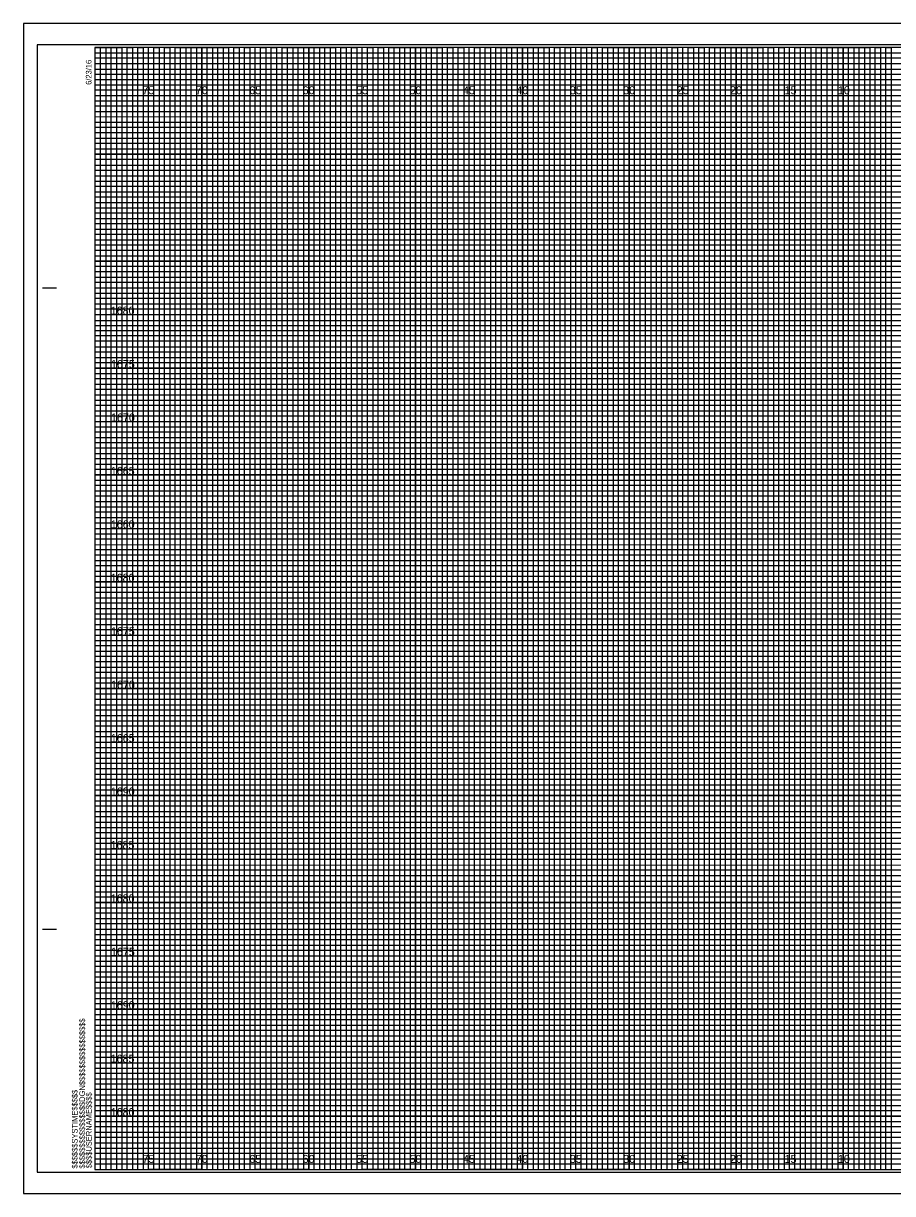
# Model space of a CAD drawing. Extents: x -7 to 162, y -2 to 107.
# Drawn here: x -6.7 to 74.6, y -2.3 to 107.3 of the extents above; entities that cross this region are included whole.
import ezdxf

# ---------------------------------------------------------------- set-up
doc = ezdxf.new("R2010")
doc.units = 0
for name, color, linetype in [('Prop XS Elevation Labels', 7, 'Continuous'), ('Prop XS Offset Labels', 7, 'Continuous'), ('Sheet Cross Section CELL', 7, 'Continuous'), ('Sheet Cross Section Grid Major CELL', 7, 'Continuous'), ('Sheet Cross Section Grid Middle CELL', 7, 'Continuous'), ('Sheet Cross Section Grid Minor 1 CELL', 7, 'Continuous'), ('Sheet Cross Section Grid Minor 2 CELL', 7, 'Continuous'), ('Sheet Cutting Line CELL', 7, 'Continuous'), ('Sheet DOT Grid CELL', 7, 'Continuous'), ('Sheet Plot Border Inside CELL', 7, 'Continuous'), ('Sheet Plot Border Outside CELL', 7, 'Continuous')]:
    doc.layers.add(name, color=color, linetype=linetype)

msp = doc.modelspace()

# ---------------------------------------------------------------- linework, layer by layer
at = {"layer": 'Sheet Cross Section CELL'}
for p, q in [((-4.9, 82.5), (-3.65, 82.5)), ((-4.85, 82.5), (-3.6, 82.5)), ((-4.9, 22.5), (-3.65, 22.5)), ((-4.85, 22.5), (-3.6, 22.5)), ((0, 0), (0, 0)), ((0, 0), (0, 0)), ((0, 0), (0, 0)), ((0, 0), (0, 0)), ((0, 0), (0, 0)), ((0, 0), (0, 0)), ((0, 0), (0, 0))]:
    msp.add_line(p, q, dxfattribs=at)
msp.add_lwpolyline([(160, 105), (0, 105), (0, 0), (160, 0)], close=True, dxfattribs=at)
at = {"layer": 'Sheet Cross Section Grid Major CELL'}
for p, q in [((5, 105), (0, 105)), ((5, 0), (5, 105)), ((15, 105), (10, 105)), ((10, 105), (10, 0)), ((15, 0), (15, 105)), ((25, 105), (20, 105)), ((20, 105), (20, 0)), ((25, 0), (25, 105)), ((35, 105), (30, 105)), ((30, 105), (30, 0)), ((35, 0), (35, 105)), ((45, 105), (40, 105)), ((40, 105), (40, 0)), ((45, 0), (45, 105)), ((55, 105), (50, 105)), ((50, 105), (50, 0)), ((55, 0), (55, 105)), ((65, 105), (60, 105)), ((60, 105), (60, 0)), ((65, 0), (65, 105)), ((75, 105), (70, 105)), ((70, 105), (70, 0)), ((10, 0), (5, 0)), ((20, 0), (15, 0)), ((30, 0), (25, 0)), ((40, 0), (35, 0)), ((50, 0), (45, 0)), ((60, 0), (55, 0)), ((70, 0), (65, 0))]:
    msp.add_line(p, q, dxfattribs=at)
for points in [[(0, 100), (160, 100), (160, 95), (0, 95)], [(0, 90), (160, 90), (160, 85), (0, 85)], [(0, 80), (160, 80), (160, 75), (0, 75)], [(0, 70), (160, 70), (160, 65), (0, 65)], [(0, 60), (160, 60), (160, 55), (0, 55)], [(0, 50), (160, 50), (160, 45), (0, 45)], [(0, 40), (160, 40), (160, 35), (0, 35)], [(0, 30), (160, 30), (160, 25), (0, 25)], [(0, 20), (160, 20), (160, 15), (0, 15)], [(0, 10), (160, 10), (160, 5), (0, 5)]]:
    msp.add_lwpolyline(points, dxfattribs=at)
at = {"layer": 'Sheet Cross Section Grid Middle CELL'}
for points in [[(0, 105), (2.5, 105), (2.5, 0), (7.5, 0), (7.5, 105), (12.5, 105), (12.5, 0), (17.5, 0), (17.5, 105), (22.5, 105), (22.5, 0), (27.5, 0), (27.5, 105), (32.5, 105), (32.5, 0), (37.5, 0), (37.5, 105), (42.5, 105), (42.5, 0), (47.5, 0), (47.5, 105), (52.5, 105), (52.5, 0), (57.5, 0), (57.5, 105), (62.5, 105), (62.5, 0), (67.5, 0), (67.5, 105), (72.5, 105), (72.5, 0), (77.5, 0)], [(0, 102.5), (137.5, 102.5)], [(0, 92.5), (160, 92.5), (160, 97.5), (0, 97.5)], [(0, 82.5), (160, 82.5), (160, 87.5), (0, 87.5)], [(0, 72.5), (160, 72.5), (160, 77.5), (0, 77.5)], [(0, 62.5), (160, 62.5), (160, 67.5), (0, 67.5)], [(0, 52.5), (160, 52.5), (160, 57.5), (0, 57.5)], [(0, 42.5), (160, 42.5), (160, 47.5), (0, 47.5)], [(0, 32.5), (160, 32.5), (160, 37.5), (0, 37.5)], [(0, 22.5), (160, 22.5), (160, 27.5), (0, 27.5)], [(0, 12.5), (160, 12.5), (160, 17.5), (0, 17.5)], [(0, 2.5), (160, 2.5), (160, 7.5), (0, 7.5)]]:
    msp.add_lwpolyline(points, dxfattribs=at)
at = {"layer": 'Sheet Cross Section Grid Minor 1 CELL'}
for p, q in [((0, 104.5), (130, 104.5)), ((130, 103.99), (0, 103.99)), ((0, 103.99), (0, 103.5)), ((0, 103.5), (130, 103.5)), ((130, 102.95), (0, 102.95)), ((0, 102.95), (0, 102)), ((0, 102), (160, 102))]:
    msp.add_line(p, q, dxfattribs=at)
for points in [[(0, 101.5), (135, 101.5), (160, 101.5), (160, 101), (0, 101)], [(0, 100.5), (160, 100.5), (160, 99.5), (0, 99.5)], [(0, 99), (160, 99), (160, 98.5), (0, 98.49)], [(0, 98), (160, 98), (160, 97), (0, 97)], [(0, 96.5), (160, 96.5), (160, 96), (0, 96)], [(0, 95.5), (160, 95.5), (160, 94.5), (0, 94.5)], [(0, 94), (160, 94), (160, 93.5), (0, 93.5)], [(0, 93), (160, 93), (160, 92), (0, 92)], [(0, 91.5), (160, 91.5), (160, 91), (0, 91)], [(0, 90.5), (160, 90.5), (160, 89.5), (0, 89.5)], [(0, 89), (160, 89), (160, 88.5), (0, 88.5)], [(0, 88), (160, 88), (160, 86.98), (160, 86.5), (160, 86), (0, 86)], [(0, 87), (160, 87), (160, 86.5), (0, 86.5)], [(0, 85.5), (160, 85.5), (160, 84.5), (0, 84.52)], [(0, 84.52), (160, 84.5), (160, 84), (0, 84)], [(0, 83.5), (160, 83.5), (160, 83), (0, 83)], [(0, 82), (160, 82), (160, 81.5), (0, 81.5)], [(0, 81), (160, 81), (160, 80.5), (0, 80.5)], [(-0.04, 79.45), (160, 79.45), (160, 78.94), (-0.04, 78.94)], [(0, 78.5), (160, 78.5), (160, 78), (0, 78)], [(0, 77), (160, 77), (160, 76.5), (0, 76.5)], [(0, 76), (160, 76), (160, 75.5), (0, 75.5)], [(0, 74.5), (160, 74.5), (160, 74), (0, 74)], [(0, 73.5), (160, 73.5), (160, 73), (0, 73)], [(0, 72), (160, 72), (160, 71.5), (0, 71.5)], [(0, 71), (160, 71), (160, 70.5), (0, 70.5)], [(0, 69.5), (160, 69.5), (160, 68.99), (0, 69)], [(0, 68.5), (160, 68.5), (160, 68), (0, 68)], [(0, 67), (160, 67), (160, 66.5), (0, 66.5)], [(0, 66), (160, 66), (160, 65.5), (0, 65.5)], [(0, 64.5), (160, 64.5), (160, 64), (0, 64)], [(0, 63.5), (160, 63.5), (160, 63), (0, 63)], [(0, 62), (160, 62), (160, 61.5), (0, 61.5)], [(0, 61), (160, 61), (160, 60.5), (0, 60.5)], [(0, 59.5), (160, 59.5), (160, 59), (0, 59)], [(0, 58.5), (160.03, 58.45), (160, 58), (0, 58)], [(0, 57), (160, 57), (160, 56.5), (0, 56.5)], [(0, 56), (160, 56), (160, 55.5), (0, 55.5)], [(0, 54.5), (160, 54.5), (160, 54), (0, 54)], [(0, 53.5), (160, 53.5), (160, 53), (0, 53)], [(0, 52), (160, 52), (160, 51.5), (0, 51.5)], [(0, 51), (160, 51), (160, 50.5), (0, 50.5)], [(0, 49.5), (160, 49.5), (160, 49), (0, 49)], [(0, 48.5), (160, 48.5), (160, 48), (0, 48)], [(0, 47), (160, 47), (160, 46.5), (0, 46.5)], [(0, 46), (160, 46), (160, 45.5), (0, 45.5)], [(0, 44.5), (160, 44.5), (160, 44), (0, 44)], [(0, 43.5), (160, 43.5), (160, 43), (0, 43)], [(0, 42), (160, 42), (160, 41.5), (0, 41.5)], [(0, 41), (160, 41), (160, 40.5), (0, 40.5)], [(0, 39.5), (160, 39.5), (160, 38.99), (0, 39)], [(0, 38.5), (160, 38.5), (160, 38), (0, 38)], [(0, 37), (160, 37), (160, 36.5), (0, 36.5)], [(0, 36), (160, 36), (160, 35.5), (0, 35.5)], [(0, 34.5), (160, 34.5), (160, 34), (0, 34)], [(0, 33.5), (160, 33.5), (160, 33), (0, 33)], [(0, 32), (160, 32), (160, 31.5), (0, 31.5)], [(0, 31), (160, 31), (160, 30.5), (0, 30.5)], [(0, 29.5), (160, 29.5), (160, 29), (0, 29)], [(0, 28.5), (160.03, 28.46), (160, 28), (0, 28)], [(0, 27), (160, 27), (160, 26.5), (0, 26.5)], [(0, 26), (160, 26), (160, 25.5), (0, 25.5)], [(0, 24.5), (160, 24.5), (160, 24), (0, 24)], [(0, 23.5), (160, 23.5), (160, 23), (0, 23)], [(0, 22), (160, 22), (160, 21.5), (0, 21.5)], [(0, 21), (160, 21), (160, 20.5), (0, 20.5)], [(0, 19.5), (160, 19.5), (160, 19), (0, 19)], [(0, 18.5), (160, 18.5), (160, 18), (0, 18)], [(0, 17), (160, 17), (160, 16.5), (0, 16.5)], [(0, 16), (160, 16), (160, 15.5), (0, 15.5)], [(0, 14.5), (160, 14.5), (160, 14), (0, 14)], [(0, 13.5), (160, 13.5), (160, 13), (0, 13)], [(0, 12), (160, 12), (160, 11.5), (0, 11.5)], [(0, 11), (160, 11), (160, 10.5), (0, 10.5)], [(0, 9.5), (160, 9.5), (160, 9), (0, 9)], [(0, 8.5), (160, 8.5), (160, 8), (0, 8)], [(0, 7), (160, 7), (160, 6.5), (0, 6.5)], [(0, 6), (160, 6), (160, 5.5), (0, 5.5)], [(0, 4.5), (160, 4.5), (160, 4), (0, 4)], [(0, 3.5), (160, 3.5), (160, 3), (0, 3)], [(0, 2), (160, 2), (160, 1.5), (0, 1.5)], [(0, 1), (160, 1), (160, 0.5), (0, 0.5)]]:
    msp.add_lwpolyline(points, dxfattribs=at)
at = {"layer": 'Sheet Cross Section Grid Minor 2 CELL'}
for points in [[(0, 0), (0.5, 0), (0.5, 105), (1, 105), (1, 0)], [(1, 0), (1.5, 0), (1.5, 105), (2, 105), (2, 0)], [(2.5, 0), (3, 0), (3, 105), (3.5, 105), (3.5, 0)], [(3.5, 0), (4, 0), (4, 105), (4.5, 105), (4.5, 0)], [(5, 0), (5.5, 0), (5.5, 105), (6, 105), (6, 0)], [(6, 0), (6.5, 0), (6.5, 105), (7, 105), (7, 0)], [(7.5, 0), (8, 0), (8, 105), (8.5, 105), (8.5, 0)], [(8.5, 0), (9, 0), (9, 105), (9.5, 105), (9.5, 0)], [(10, 0), (10.5, 0), (10.5, 105), (11, 105), (11, 0)], [(11, 0), (11.5, 0), (11.5, 105), (12, 105), (12, 0)], [(12.5, 0), (13, 0), (13, 105), (13.5, 105), (13.5, 0)], [(13.5, 0), (14, 0), (14, 105), (14.5, 105), (14.5, 0)], [(15, 0), (15.5, 0), (15.5, 105), (16, 105), (16, 0)], [(16, 0), (16.5, 0), (16.5, 105), (17, 105), (17, 0)], [(17.5, 0), (18, 0), (18, 105), (18.5, 105), (18.5, 0)], [(18.5, 0), (19, 0), (19, 105), (19.5, 105), (19.5, 0)], [(20, 0), (20.5, 0), (20.5, 105), (21, 105), (21, 0)], [(21, 0), (21.5, 0), (21.5, 105), (22, 105), (22, 0)], [(22.5, 0), (23, 0), (23, 105), (23.5, 105), (23.5, 0)], [(23.5, 0), (24, 0), (24, 105), (24.5, 105), (24.5, 0)], [(25, 0), (25.5, 0), (25.5, 105), (26, 105), (26, 0)], [(26, 0), (26.5, 0), (26.5, 105), (27, 105), (27, 0)], [(27.5, 0), (28, 0), (28, 105), (28.5, 105), (28.5, 0)], [(28.5, 0), (29, 0), (29, 105), (29.5, 105), (29.5, 0)], [(30, 0), (30.5, 0), (30.5, 105), (31, 105), (31, 0)], [(31, 0), (31.5, 0), (31.5, 105), (32, 105), (32, 0)], [(32.5, 0), (33, 0), (33, 105), (33.5, 105), (33.5, 0)], [(33.5, 0), (34, 0), (34, 105), (34.5, 105), (34.5, 0)], [(35, 0), (35.5, 0), (35.5, 105), (36, 105), (36, 0)], [(36, 0), (36.5, 0), (36.5, 105), (37, 105), (37, 0)], [(37.5, 0), (38, 0), (38, 105), (38.5, 105), (38.5, 0)], [(38.5, 0), (39, 0), (39, 105), (39.5, 105), (39.5, 0)], [(40, 0), (40.5, 0), (40.5, 105), (41, 105), (41, 0)], [(41, 0), (41.5, 0), (41.5, 105), (42, 105), (42, 0)], [(42.5, 0), (43, 0), (43, 105), (43.5, 105), (43.5, 0)], [(43.5, 0), (44, 0), (44, 105), (44.5, 105), (44.5, 0)], [(45, 0), (45.5, 0), (45.5, 105), (46, 105), (46, 0)], [(46, 0), (46.5, 0), (46.5, 105), (47, 105), (47, 0)], [(47.5, 0), (48, 0), (48, 105), (48.5, 105), (48.5, 0)], [(48.5, 0), (49, 0), (49, 105), (49.5, 105), (49.5, 0)], [(50, 0), (50.5, 0), (50.5, 105), (51, 105), (51, 0)], [(51, 0), (51.5, 0), (51.5, 105), (52, 105), (52, 0)], [(52.5, 0), (53, 0), (53, 105), (53.5, 105), (53.5, 0)], [(53.5, 0), (54, 0), (54, 105), (54.5, 105), (54.5, 0)], [(55, 0), (55.5, 0), (55.5, 105), (56, 105), (56, 0)], [(56, 0), (56.5, 0), (56.5, 105), (57, 105), (57, 0)], [(57.5, 0), (58, 0), (58, 105), (58.5, 105), (58.5, 0)], [(58.5, 0), (59, 0), (59, 105), (59.5, 105), (59.5, 0)], [(60, 0), (60.5, 0), (60.5, 105), (61, 105), (61, 0)], [(61, 0), (61.5, 0), (61.5, 105), (62, 105), (62, 0)], [(62.5, 0), (63, 0), (63, 105), (63.5, 105), (63.5, 0)], [(63.5, 0), (64, 0), (64, 105), (64.5, 105), (64.5, 0)], [(65, 0), (65.5, 0), (65.5, 105), (66, 105), (66, 0)], [(66, 0), (66.5, 0), (66.5, 105), (67, 105), (67, 0)], [(67.5, 0), (68, 0), (68, 105), (68.5, 105), (68.5, 0)], [(68.5, 0), (69, 0), (69, 105), (69.5, 105), (69.5, 0)], [(70, 0), (70.5, 0), (70.5, 105), (71, 105), (71, 0)], [(71, 0), (71.5, 0), (71.5, 105), (72, 105), (72, 0)], [(72.5, 0), (73, 0), (73, 105), (73.5, 105), (73.5, 0)], [(73.5, 0), (74, 0), (74, 105), (74.5, 105), (74.5, 0)]]:
    msp.add_lwpolyline(points, dxfattribs=at)
at = {"layer": 'Sheet Cutting Line CELL'}
for p, q in [((161.65, 107.25), (-6.7, 107.25)), ((-6.7, 107.25), (-6.7, -2.25)), ((-6.7, -2.25), (161.65, -2.25))]:
    msp.add_line(p, q, dxfattribs=at)
at = {"layer": 'Sheet DOT Grid CELL'}
for p, q in [((5, 0), (5, 105)), ((10, 0), (10, 105)), ((15, 0), (15, 105)), ((20, 0), (20, 105)), ((25, 0), (25, 105)), ((30, 0), (30, 105)), ((35, 0), (35, 105)), ((40, 0), (40, 105)), ((45, 0), (45, 105)), ((50, 0), (50, 105)), ((55, 0), (55, 105)), ((60, 0), (60, 105)), ((65, 0), (65, 105)), ((70, 0), (70, 105)), ((0, 100), (160, 100)), ((0, 95), (160, 95)), ((0, 90), (160, 90)), ((0, 85), (160, 85)), ((0, 80), (160, 80)), ((0, 75), (160, 75)), ((0, 70), (160, 70)), ((0, 65), (160, 65)), ((0, 60), (160, 60)), ((0, 55), (160, 55)), ((0, 50), (160, 50)), ((0, 45), (160, 45)), ((0, 40), (160, 40)), ((0, 35), (160, 35)), ((0, 30), (160, 30)), ((0, 25), (160, 25)), ((0, 20), (160, 20)), ((0, 15), (160, 15)), ((0, 10), (160, 10)), ((0, 5), (160, 5))]:
    msp.add_line(p, q, dxfattribs=at)
at = {"layer": 'Sheet Plot Border Inside CELL'}
msp.add_lwpolyline([(-5.4, -0.25), (161.2, -0.25), (161.2, 105.25), (-5.4, 105.25)], close=True, dxfattribs=at)
at = {"layer": 'Sheet Plot Border Outside CELL'}
msp.add_lwpolyline([(-6.7, -2.25), (161.65, -2.25), (161.65, 107.25), (-6.7, 107.25)], close=True, dxfattribs=at)

# ---------------------------------------------------------------- texts
at = {"layer": 'Prop XS Elevation Labels'}
for s, p in [('1680', (1.47, 80)), ('1675', (1.49, 75)), ('1670', (1.5, 70)), ('1665', (1.48, 65)), ('1660', (1.48, 60)), ('1680', (1.47, 55)), ('1675', (1.49, 50)), ('1670', (1.5, 45)), ('1665', (1.48, 40)), ('1690', (1.48, 35)), ('1685', (1.46, 30)), ('1680', (1.47, 25)), ('1675', (1.49, 20)), ('1690', (1.48, 15)), ('1685', (1.46, 10)), ('1680', (1.47, 5))]:
    msp.add_text(s, height=0.75, dxfattribs=at).set_placement(p)
at = {"layer": 'Prop XS Offset Labels'}
for s, p in [('75', (4.44, 100.62)), ('70', (9.43, 100.62)), ('65', (14.44, 100.62)), ('60', (19.43, 100.62)), ('55', (24.44, 100.62)), ('50', (29.43, 100.62)), ('45', (34.44, 100.62)), ('40', (39.43, 100.62)), ('35', (44.44, 100.62)), ('30', (49.43, 100.62)), ('25', (54.44, 100.62)), ('20', (59.43, 100.62)), ('15', (64.53, 100.62)), ('10', (69.52, 100.62)), ('75', (4.44, 0.62)), ('70', (9.43, 0.62)), ('65', (14.44, 0.62)), ('60', (19.43, 0.62)), ('55', (24.44, 0.62)), ('50', (29.43, 0.62)), ('45', (34.44, 0.62)), ('40', (39.43, 0.62)), ('35', (44.44, 0.62)), ('30', (49.43, 0.62)), ('25', (54.44, 0.62)), ('20', (59.43, 0.62)), ('15', (64.53, 0.62)), ('10', (69.52, 0.62))]:
    msp.add_text(s, height=0.75, dxfattribs=at).set_placement(p)
at = {"layer": 'Sheet Cross Section CELL'}
for s, p in [('6/23/16', (-0.33, 101.5)), ('$$$$$$$$$$$$$$$$DGN$$$$$$$$$$$$$$$$', (-0.94, 0.09)), ('$$$$$$SYSTIME$$$$$', (-1.63, 0.09)), ('$$$$USERNAME$$$$', (-0.31, 0.12))]:
    msp.add_text(s, height=0.525, rotation=90, dxfattribs=at).set_placement(p)

doc.saveas('drawing.dxf')
